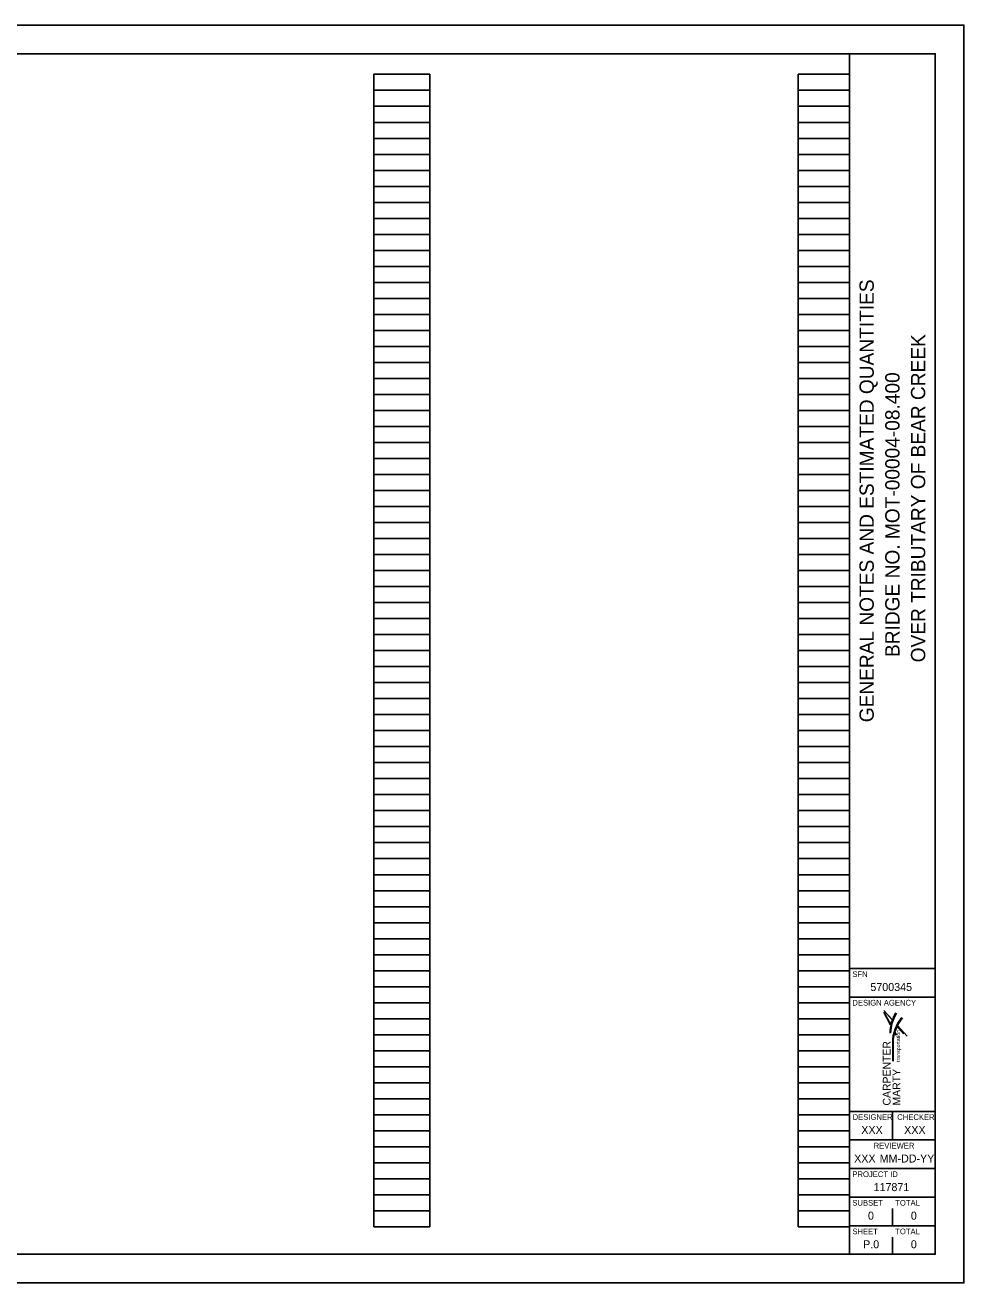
# Model space of a CAD drawing. Extents: x 0 to 34, y 0 to 22.
# Drawn here: x 17.58 to 34, y 0 to 22 of the extents above; entities that cross this region are included whole.
import ezdxf

# ---------------------------------------------------------------- set-up
doc = ezdxf.new("R2010")
doc.units = 0
for name, color, linetype in [('SH_Border', 7, 'Continuous'), ('SH_Cut_Line', 7, 'Continuous'), ('SH_Data', 7, 'Continuous'), ('SH_Text', 7, 'Continuous')]:
    doc.layers.add(name, color=color, linetype=linetype)

msp = doc.modelspace()

# ---------------------------------------------------------------- linework, layer by layer
at = {"layer": 'SH_Border'}
for p, q in [((32, 0.5), (32, 21.5)), ((32, 5.5), (33.5, 5.5)), ((32, 5), (33.5, 5)), ((32, 3), (33.5, 3)), ((32.75, 3), (32.75, 2.5)), ((32, 2.5), (33.5, 2.5)), ((32, 2), (33.5, 2)), ((32, 1.5), (33.5, 1.5)), ((32, 1), (33.5, 1))]:
    msp.add_line(p, q, dxfattribs=at)
msp.add_lwpolyline([(1.5, 21.5), (33.5, 21.5), (33.5, 0.5), (1.5, 0.5)], close=True, dxfattribs=at)
at = {"layer": 'SH_Cut_Line'}
msp.add_lwpolyline([(0, 0), (34, 0), (34, 22), (0, 22)], close=True, dxfattribs=at)
at = {"layer": 'SH_Data'}
for p, q in [((23.68, 0.98), (23.68, 21.14)), ((23.68, 21.14), (24.66, 21.14)), ((24.66, 0.98), (24.66, 21.14)), ((31.1, 0.98), (31.1, 21.14)), ((31.1, 21.14), (32, 21.14)), ((32, 0.98), (32, 21.14)), ((23.68, 20.86), (24.66, 20.86)), ((31.1, 20.86), (32, 20.86)), ((23.68, 20.58), (24.66, 20.58)), ((31.1, 20.58), (32, 20.58)), ((23.68, 20.3), (24.66, 20.3)), ((31.1, 20.3), (32, 20.3)), ((23.68, 20.02), (24.66, 20.02)), ((31.1, 20.02), (32, 20.02)), ((23.68, 19.74), (24.66, 19.74)), ((31.1, 19.74), (32, 19.74)), ((23.68, 19.46), (24.66, 19.46)), ((31.1, 19.46), (32, 19.46)), ((23.68, 19.18), (24.66, 19.18)), ((31.1, 19.18), (32, 19.18)), ((23.68, 18.9), (24.66, 18.9)), ((31.1, 18.9), (32, 18.9)), ((23.68, 18.62), (24.66, 18.62)), ((31.1, 18.62), (32, 18.62)), ((23.68, 18.34), (24.66, 18.34)), ((31.1, 18.34), (32, 18.34)), ((23.68, 18.06), (24.66, 18.06)), ((31.1, 18.06), (32, 18.06)), ((23.68, 17.78), (24.66, 17.78)), ((31.1, 17.78), (32, 17.78)), ((23.68, 17.5), (24.66, 17.5)), ((31.1, 17.5), (32, 17.5)), ((23.68, 17.22), (24.66, 17.22)), ((31.1, 17.22), (32, 17.22)), ((23.68, 16.94), (24.66, 16.94)), ((31.1, 16.94), (32, 16.94)), ((23.68, 16.66), (24.66, 16.66)), ((31.1, 16.66), (32, 16.66)), ((23.68, 16.38), (24.66, 16.38)), ((31.1, 16.38), (32, 16.38)), ((23.68, 16.1), (24.66, 16.1)), ((31.1, 16.1), (32, 16.1)), ((23.68, 15.82), (24.66, 15.82)), ((31.1, 15.82), (32, 15.82)), ((23.68, 15.54), (24.66, 15.54)), ((31.1, 15.54), (32, 15.54)), ((23.68, 15.26), (24.66, 15.26)), ((31.1, 15.26), (32, 15.26)), ((23.68, 14.98), (24.66, 14.98)), ((31.1, 14.98), (32, 14.98)), ((23.68, 14.7), (24.66, 14.7)), ((31.1, 14.7), (32, 14.7)), ((23.68, 14.42), (24.66, 14.42)), ((31.1, 14.42), (32, 14.42)), ((23.68, 14.14), (24.66, 14.14)), ((31.1, 14.14), (32, 14.14)), ((23.68, 13.86), (24.66, 13.86)), ((31.1, 13.86), (32, 13.86)), ((23.68, 13.58), (24.66, 13.58)), ((31.1, 13.58), (32, 13.58)), ((23.68, 13.3), (24.66, 13.3)), ((31.1, 13.3), (32, 13.3)), ((23.68, 13.02), (24.66, 13.02)), ((31.1, 13.02), (32, 13.02)), ((23.68, 12.74), (24.66, 12.74)), ((31.1, 12.74), (32, 12.74)), ((23.68, 12.46), (24.66, 12.46)), ((31.1, 12.46), (32, 12.46)), ((23.68, 12.18), (24.66, 12.18)), ((31.1, 12.18), (32, 12.18)), ((23.68, 11.9), (24.66, 11.9)), ((31.1, 11.9), (32, 11.9)), ((23.68, 11.62), (24.66, 11.62)), ((31.1, 11.62), (32, 11.62)), ((23.68, 11.34), (24.66, 11.34)), ((31.1, 11.34), (32, 11.34)), ((23.68, 11.06), (24.66, 11.06)), ((31.1, 11.06), (32, 11.06)), ((23.68, 10.78), (24.66, 10.78)), ((31.1, 10.78), (32, 10.78)), ((23.68, 10.5), (24.66, 10.5)), ((31.1, 10.5), (32, 10.5)), ((23.68, 10.22), (24.66, 10.22)), ((31.1, 10.22), (32, 10.22)), ((23.68, 9.94), (24.66, 9.94)), ((31.1, 9.94), (32, 9.94)), ((23.68, 9.66), (24.66, 9.66)), ((31.1, 9.66), (32, 9.66)), ((23.68, 9.38), (24.66, 9.38)), ((31.1, 9.38), (32, 9.38)), ((23.68, 9.1), (24.66, 9.1)), ((31.1, 9.1), (32, 9.1)), ((23.68, 8.82), (24.66, 8.82)), ((31.1, 8.82), (32, 8.82)), ((23.68, 8.54), (24.66, 8.54)), ((31.1, 8.54), (32, 8.54)), ((23.68, 8.26), (24.66, 8.26)), ((31.1, 8.26), (32, 8.26)), ((23.68, 7.98), (24.66, 7.98)), ((31.1, 7.98), (32, 7.98)), ((23.68, 7.7), (24.66, 7.7)), ((31.1, 7.7), (32, 7.7)), ((23.68, 7.42), (24.66, 7.42)), ((31.1, 7.42), (32, 7.42)), ((23.68, 7.14), (24.66, 7.14)), ((31.1, 7.14), (32, 7.14)), ((23.68, 6.86), (24.66, 6.86)), ((31.1, 6.86), (32, 6.86)), ((23.68, 6.58), (24.66, 6.58)), ((31.1, 6.58), (32, 6.58)), ((23.68, 6.3), (24.66, 6.3)), ((31.1, 6.3), (32, 6.3)), ((23.68, 6.02), (24.66, 6.02)), ((31.1, 6.02), (32, 6.02)), ((23.68, 5.74), (24.66, 5.74)), ((31.1, 5.74), (32, 5.74)), ((23.68, 5.46), (24.66, 5.46)), ((31.1, 5.46), (32, 5.46)), ((23.68, 5.18), (24.66, 5.18)), ((31.1, 5.18), (32, 5.18)), ((23.68, 4.9), (24.66, 4.9)), ((31.1, 4.9), (32, 4.9)), ((23.68, 4.62), (24.66, 4.62)), ((31.1, 4.62), (32, 4.62)), ((23.68, 4.34), (24.66, 4.34)), ((31.1, 4.34), (32, 4.34)), ((23.68, 4.06), (24.66, 4.06)), ((31.1, 4.06), (32, 4.06)), ((32.75, 4), (32.75, 4)), ((23.68, 3.78), (24.66, 3.78)), ((31.1, 3.78), (32, 3.78)), ((23.68, 3.5), (24.66, 3.5)), ((31.1, 3.5), (32, 3.5)), ((23.68, 3.22), (24.66, 3.22)), ((31.1, 3.22), (32, 3.22)), ((23.68, 2.94), (24.66, 2.94)), ((31.1, 2.94), (32, 2.94)), ((23.68, 2.66), (24.66, 2.66)), ((31.1, 2.66), (32, 2.66)), ((23.68, 2.38), (24.66, 2.38)), ((31.1, 2.38), (32, 2.38)), ((23.68, 2.1), (24.66, 2.1)), ((31.1, 2.1), (32, 2.1)), ((23.68, 1.82), (24.66, 1.82)), ((31.1, 1.82), (32, 1.82)), ((23.68, 1.54), (24.66, 1.54)), ((31.1, 1.54), (32, 1.54)), ((23.68, 1.26), (24.66, 1.26)), ((31.1, 1.26), (32, 1.26)), ((32.75, 1), (32.75, 1.3)), ((23.68, 0.98), (24.66, 0.98)), ((31.1, 0.98), (32, 0.98)), ((32.375, 0.675), (32.375, 0.675)), ((32.75, 0.5), (32.75, 0.8))]:
    msp.add_line(p, q, dxfattribs=at)
at = {"layer": 'SH_Text'}
for p, q in [((32.721, 4.516), (32.602, 4.732)), ((32.952, 4.353), (32.834, 4.491)), ((32.839, 4.502), (33.006, 4.316)), ((32.755, 3.878), (32.755, 4.204)), ((32.762, 3.878), (32.762, 4.204)), ((32.811, 4.34), (32.79, 4.38)), ((32.82, 4.334), (32.791, 4.386))]:
    msp.add_line(p, q, dxfattribs=at)
for points in [[(32.746, 4.604), (32.601, 4.766)], [(32.601, 4.766), (32.744, 4.598)], [(32.721, 4.516), (32.602, 4.732)], [(32.602, 4.732), (32.719, 4.511)]]:
    msp.add_lwpolyline(points, dxfattribs=at)
for centre, radius, start, end in [((33.432, 4.36), 0.721, 149.5704, 179.5529), ((33.373, 4.362), 0.654, 147.1423, 179.6525), ((33.426, 4.204), 0.671, 139.2898, 180.0106), ((33.433, 4.188), 0.672, 138.5126, 178.6075)]:
    msp.add_arc(centre, radius, start, end, dxfattribs=at)

# ---------------------------------------------------------------- texts
at = {"layer": 'SH_Data'}
for s, p in [('GENERAL NOTES AND ESTIMATED QUANTITIES', (32.425, 9.806)), ('OVER TRIBUTARY OF BEAR CREEK', (33.325, 10.854)), ('BRIDGE NO. MOT-00004-08.400', (32.875, 10.948))]:
    msp.add_text(s, height=0.25, rotation=90, dxfattribs=at).set_placement(p)
for s, height, p in [('SFN', 0.1, (32.05, 5.35)), ('5700345', 0.14, (32.365, 5.105)), ('DESIGN AGENCY', 0.1, (32.05, 4.85)), ('DESIGNER', 0.1, (32.054, 2.85)), ('CHECKER', 0.1, (32.835, 2.85)), ('XXX', 0.14, (32.206, 2.605)), ('XXX', 0.14, (32.956, 2.605)), ('REVIEWER', 0.1, (32.422, 2.35)), ('XXX', 0.14, (32.081, 2.105)), ('MM-DD-YY', 0.14, (32.527, 2.105)), ('PROJECT ID', 0.1, (32.05, 1.85)), ('117871', 0.14, (32.421, 1.605)), ('SUBSET', 0.1, (32.05, 1.35)), ('TOTAL', 0.1, (32.8, 1.35)), ('0', 0.14, (32.323, 1.105)), ('0', 0.14, (33.073, 1.105)), ('SHEET', 0.1, (32.05, 0.85)), ('TOTAL', 0.1, (32.8, 0.85)), ('P.0', 0.14, (32.238, 0.605)), ('0', 0.14, (33.073, 0.605))]:
    msp.add_text(s, height=height, dxfattribs=at).set_placement(p)
at = {"layer": 'SH_Text'}
for s, height, p in [('transportation', 0.06649, (32.885, 3.864)), ('CARPENTER ', 0.1367, (32.719, 3.102)), ('MARTY', 0.1367, (32.891, 3.102))]:
    msp.add_text(s, height=height, rotation=90, dxfattribs=at).set_placement(p)

doc.saveas('drawing.dxf')
